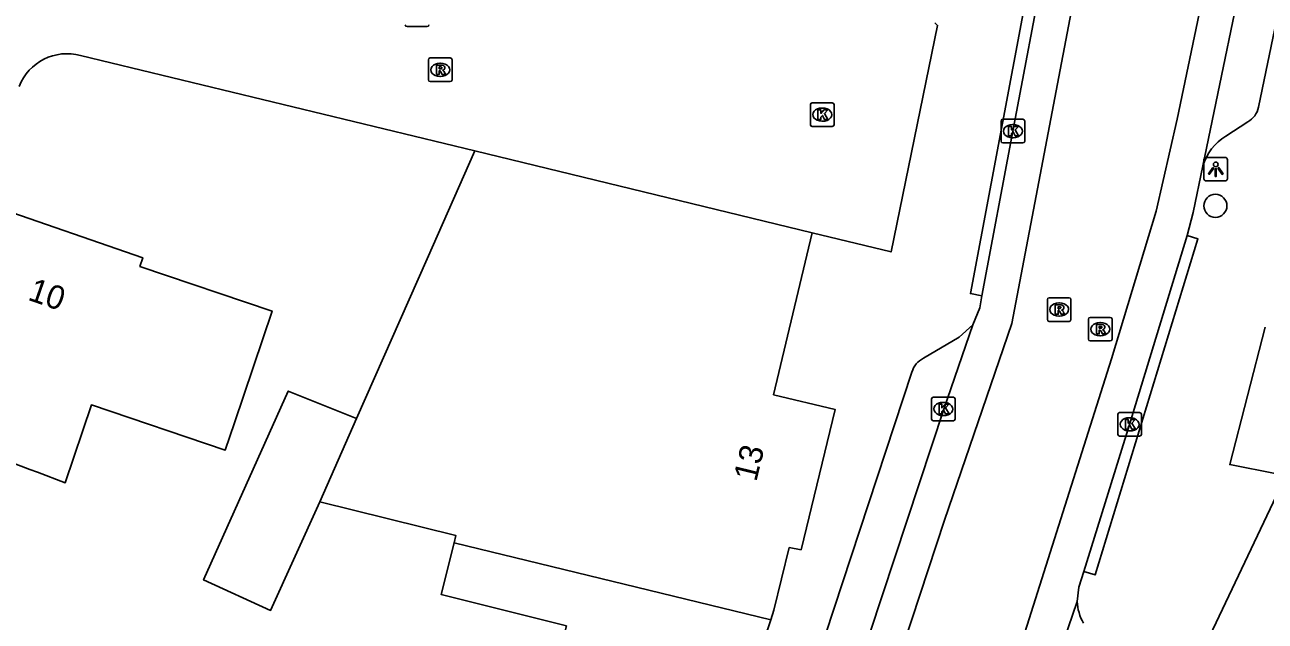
# Model space of a CAD drawing. Extents: x 160037 to 160839, y 385326 to 386441.
# Drawn here: x 160667.7 to 160720.3, y 385444.3 to 385469.6 of the extents above; entities that cross this region are included whole.
import ezdxf

# ---------------------------------------------------------------- set-up
doc = ezdxf.new("R2010")
doc.units = 0
for name, color, linetype in [('IMGEO_Boom', 7, 'Continuous'), ('IMGEO_Kolk', 7, 'Continuous'), ('IMGEO_Lichtpunt', 7, 'Continuous'), ('IMGEO_Pand', 7, 'Continuous'), ('IMGEO_Pand_nummerreeks', 7, 'Continuous'), ('IMGEO_Rijbaan_lokaal_gesloten', 7, 'Continuous'), ('IMGEO_Rijbaan_lokaal_open', 7, 'Continuous'), ('IMGEO_Rioolput', 7, 'Continuous'), ('IMGEO_Voetpad_open', 7, 'Continuous')]:
    doc.layers.add(name, color=color, linetype=linetype)

msp = doc.modelspace()

# ---------------------------------------------------------------- linework, layer by layer
at = {"layer": 'IMGEO_Boom'}
msp.add_circle((160718.188, 385461.911), 0.489, dxfattribs=at)
at = {"layer": 'IMGEO_Kolk'}
for p, q in [((160684.75, 385469.514), (160683.898, 385469.514)), ((160701.008, 385465.353), (160701.008, 385466.205)), ((160701.083, 385466.279), (160701.935, 385466.279)), ((160701.496, 385466.059), (160701.521, 385466.059)), ((160702.009, 385466.205), (160702.009, 385465.353)), ((160701.519, 385465.499), (160701.494, 385465.499)), ((160709.095, 385464.655), (160709.095, 385465.507)), ((160709.17, 385465.581), (160710.022, 385465.581)), ((160709.583, 385465.361), (160709.608, 385465.361)), ((160710.096, 385465.507), (160710.096, 385464.655)), ((160701.935, 385465.279), (160701.083, 385465.279)), ((160710.022, 385464.581), (160709.17, 385464.581)), ((160709.606, 385464.801), (160709.581, 385464.801)), ((160706.22, 385453.795), (160707.072, 385453.795)), ((160706.145, 385452.869), (160706.145, 385453.721)), ((160706.633, 385453.575), (160706.658, 385453.575)), ((160707.146, 385453.721), (160707.146, 385452.869)), ((160707.072, 385452.795), (160706.22, 385452.795)), ((160706.656, 385453.015), (160706.631, 385453.015)), ((160714.047, 385452.218), (160714.047, 385453.07)), ((160714.122, 385453.144), (160714.974, 385453.144)), ((160714.535, 385452.924), (160714.56, 385452.924)), ((160715.048, 385453.07), (160715.048, 385452.218)), ((160714.558, 385452.364), (160714.533, 385452.364)), ((160714.974, 385452.144), (160714.122, 385452.144))]:
    msp.add_line(p, q, dxfattribs=at)
for points in [[(160684.75, 385469.514), (160683.898, 385469.514)], [(160701.008, 385465.353), (160701.008, 385466.205)], [(160701.083, 385466.279), (160701.935, 385466.279)], [(160701.329, 385465.979), (160701.452, 385465.979), (160701.452, 385465.828), (160701.582, 385465.979), (160701.746, 385465.979), (160701.6, 385465.828), (160701.753, 385465.579), (160701.601, 385465.579), (160701.516, 385465.743), (160701.452, 385465.676), (160701.452, 385465.579), (160701.329, 385465.579), (160701.329, 385465.979)], [(160702.009, 385466.205), (160702.009, 385465.353)], [(160709.095, 385464.655), (160709.095, 385465.507)], [(160709.17, 385465.581), (160710.022, 385465.581)], [(160710.096, 385465.507), (160710.096, 385464.655)], [(160701.935, 385465.279), (160701.083, 385465.279)], [(160709.416, 385465.281), (160709.539, 385465.281), (160709.539, 385465.13), (160709.669, 385465.281), (160709.833, 385465.281), (160709.687, 385465.13), (160709.84, 385464.881), (160709.688, 385464.881), (160709.603, 385465.045), (160709.539, 385464.978), (160709.539, 385464.881), (160709.416, 385464.881), (160709.416, 385465.281)], [(160710.022, 385464.581), (160709.17, 385464.581)], [(160706.22, 385453.795), (160707.072, 385453.795)], [(160706.145, 385452.869), (160706.145, 385453.721)], [(160706.466, 385453.495), (160706.589, 385453.495), (160706.589, 385453.344), (160706.719, 385453.495), (160706.883, 385453.495), (160706.737, 385453.344), (160706.89, 385453.095), (160706.738, 385453.095), (160706.653, 385453.259), (160706.589, 385453.192), (160706.589, 385453.095), (160706.466, 385453.095), (160706.466, 385453.495)], [(160707.146, 385453.721), (160707.146, 385452.869)], [(160707.072, 385452.795), (160706.22, 385452.795)], [(160714.047, 385452.218), (160714.047, 385453.07)], [(160714.122, 385453.144), (160714.974, 385453.144)], [(160714.368, 385452.844), (160714.491, 385452.844), (160714.491, 385452.693), (160714.621, 385452.844), (160714.785, 385452.844), (160714.639, 385452.693), (160714.792, 385452.444), (160714.64, 385452.444), (160714.555, 385452.608), (160714.491, 385452.541), (160714.491, 385452.444), (160714.368, 385452.444), (160714.368, 385452.844)], [(160715.048, 385453.07), (160715.048, 385452.218)], [(160714.974, 385452.144), (160714.122, 385452.144)]]:
    msp.add_lwpolyline(points, dxfattribs=at)
for centre, start, end in [((160683.9, 385469.59), 181.552, 268.448), ((160683.9, 385469.59), 181.552, 268.448), ((160684.748, 385469.59), 271.552, 358.448), ((160684.748, 385469.59), 271.552, 358.448), ((160701.085, 385466.203), 91.552, 178.448), ((160701.085, 385466.203), 91.552, 178.448), ((160701.933, 385466.203), 1.552, 88.448), ((160701.933, 385466.203), 1.552, 88.448), ((160701.085, 385465.355), 181.552, 268.448), ((160701.085, 385465.355), 181.552, 268.448), ((160701.933, 385465.355), 271.552, 358.448), ((160701.933, 385465.355), 271.552, 358.448), ((160709.172, 385465.505), 91.552, 178.448), ((160709.172, 385465.505), 91.552, 178.448), ((160710.02, 385465.505), 1.552, 88.448), ((160710.02, 385465.505), 1.552, 88.448), ((160709.172, 385464.657), 181.552, 268.448), ((160709.172, 385464.657), 181.552, 268.448), ((160710.02, 385464.657), 271.552, 358.448), ((160710.02, 385464.657), 271.552, 358.448), ((160706.222, 385453.719), 91.552, 178.448), ((160706.222, 385453.719), 91.552, 178.448), ((160707.07, 385453.719), 1.552, 88.448), ((160707.07, 385453.719), 1.552, 88.448), ((160706.222, 385452.871), 181.552, 268.448), ((160706.222, 385452.871), 181.552, 268.448), ((160707.07, 385452.871), 271.552, 358.448), ((160707.07, 385452.871), 271.552, 358.448), ((160714.124, 385453.068), 91.552, 178.448), ((160714.124, 385453.068), 91.552, 178.448), ((160714.972, 385453.068), 1.552, 88.448), ((160714.972, 385453.068), 1.552, 88.448), ((160714.124, 385452.22), 181.552, 268.448), ((160714.124, 385452.22), 181.552, 268.448), ((160714.972, 385452.22), 271.552, 358.448), ((160714.972, 385452.22), 271.552, 358.448)]:
    msp.add_arc(centre, 0.0765, start, end, dxfattribs=at)
for centre, major_axis, ratio, start_param, end_param in [((160701.495, 385465.779), (-0.387, 0.002), 0.722429, 4.712389, 7.853982), ((160701.52, 385465.779), (-0.39, 0.002), 0.717154, 1.570796, 4.712389), ((160709.582, 385465.081), (-0.387, 0.002), 0.722429, 4.712389, 7.853982), ((160709.607, 385465.081), (-0.39, 0.002), 0.717154, 1.570796, 4.712389), ((160706.632, 385453.295), (-0.387, 0.002), 0.722429, 4.712389, 7.853982), ((160706.657, 385453.295), (-0.39, 0.002), 0.717154, 1.570796, 4.712389), ((160714.534, 385452.644), (-0.387, 0.002), 0.722429, 4.712389, 7.853982), ((160714.559, 385452.644), (-0.39, 0.002), 0.717154, 1.570796, 4.712389)]:
    msp.add_ellipse(centre, major_axis=major_axis, ratio=ratio, start_param=start_param, end_param=end_param, dxfattribs=at)
at = {"layer": 'IMGEO_Lichtpunt'}
for p, q in [((160717.702, 385463.868), (160717.702, 385463.061)), ((160717.702, 385463.868), (160717.702, 385463.061)), ((160718.604, 385463.963), (160717.796, 385463.963)), ((160718.604, 385463.963), (160717.796, 385463.963)), ((160718.698, 385463.061), (160718.698, 385463.868)), ((160718.698, 385463.061), (160718.698, 385463.868)), ((160717.796, 385462.967), (160718.604, 385462.967)), ((160717.796, 385462.967), (160718.604, 385462.967))]:
    msp.add_line(p, q, dxfattribs=at)
for points in [[(160718.076, 385463.532), (160718.115, 385463.504), (160717.927, 385463.242), (160717.889, 385463.269), (160718.076, 385463.532)], [(160718.178, 385463.484), (160718.225, 385463.484), (160718.225, 385463.162), (160718.178, 385463.162), (160718.178, 385463.484)], [(160718.288, 385463.504), (160718.326, 385463.531), (160718.513, 385463.269), (160718.474, 385463.241), (160718.288, 385463.504)]]:
    msp.add_lwpolyline(points, dxfattribs=at)
msp.add_circle((160718.201, 385463.666), 0.0994, dxfattribs=at)
for centre, start, end in [((160717.796, 385463.868), 90, 180), ((160717.796, 385463.868), 90, 180), ((160718.604, 385463.868), 0, 90), ((160718.604, 385463.868), 0, 90), ((160717.796, 385463.061), 180, 270), ((160717.796, 385463.061), 180, 270), ((160718.604, 385463.061), 270, 0), ((160718.604, 385463.061), 270, 360)]:
    msp.add_arc(centre, 0.0946, start, end, dxfattribs=at)
at = {"layer": 'IMGEO_Pand'}
for points in [[(160681.758, 385452.889), (160684.749, 385459.664), (160686.769, 385464.238)], [(160701.081, 385460.769), (160686.769, 385464.238)], [(160666.377, 385461.884), (160672.687, 385459.709), (160672.563, 385459.34), (160678.174, 385457.45), (160676.578, 385452.712), (160676.189, 385451.556), (160670.512, 385453.469), (160669.4, 385450.17), (160668.215, 385450.615), (160667.903, 385450.732), (160667.042, 385451.055), (160666.812, 385450.423), (160666.627, 385449.911), (160666.038, 385448.288), (160663.09, 385449.283), (160662.224, 385449.557), (160666.377, 385461.884)], [(160699.328, 385444.361), (160699.463, 385444.758), (160700.107, 385447.418), (160700.612, 385447.327), (160702.051, 385453.278), (160699.442, 385453.9), (160701.081, 385460.769)], [(160680.2, 385449.359), (160678.107, 385444.753), (160675.266, 385446.044), (160678.857, 385454.058), (160681.758, 385452.889)], [(160681.758, 385452.889), (160680.2, 385449.359)], [(160685.894, 385447.621), (160685.971, 385447.927), (160680.2, 385449.359)], [(160697.856, 385440.02), (160693.008, 385441.24), (160690.122, 385441.967), (160690.658, 385444.096), (160685.343, 385445.434), (160685.894, 385447.621)], [(160699.328, 385444.361), (160685.894, 385447.621)], [(160697.856, 385440.02), (160699.328, 385444.361)]]:
    msp.add_lwpolyline(points, dxfattribs=at)
at = {"layer": 'IMGEO_Rijbaan_lokaal_gesloten'}
for points in [[(160690.447, 385399.194), (160706.697, 385448.575), (160709.556, 385456.928), (160712.459, 385472.214), (160719.187, 385500), (160719.283, 385500.396)], [(160723.639, 385499.449), (160716.569, 385465.593), (160715.669, 385461.679), (160713.786, 385455.424), (160707.954, 385437.031), (160694.523, 385397.769)], [(160725.06, 385499.141), (160724.626, 385497.095), (160719.791, 385473.917), (160717.66, 385463.602)], [(160710.963, 385472.336), (160709.594, 385465.081), (160708.283, 385458.1)], [(160717.66, 385463.602), (160717.24, 385461.622), (160716.992, 385460.652)], [(160712.604, 385446.405), (160714.549, 385452.643), (160716.992, 385460.652)], [(160708.283, 385458.1), (160708.191, 385457.591), (160707.895, 385456.866)], [(160688.951, 385399.714), (160690.313, 385403.559), (160696.35, 385421.936), (160701.443, 385437.493), (160706.661, 385453.29), (160707.895, 385456.866)], [(160712.604, 385446.405), (160712.4, 385445.745), (160712.326, 385445.138)], [(160712.326, 385445.138), (160709.47, 385436.771), (160703.7, 385419.94), (160695.958, 385397.266)]]:
    msp.add_lwpolyline(points, dxfattribs=at)
at = {"layer": 'IMGEO_Rijbaan_lokaal_open'}
for points in [[(160701.081, 385460.769), (160704.431, 385459.957), (160706.404, 385469.564), (160706.283, 385469.675)], [(160686.769, 385464.238), (160670.05, 385468.291)], [(160720.793, 385450.546), (160718.792, 385450.935), (160720.304, 385456.764)]]:
    msp.add_lwpolyline(points, dxfattribs=at)
msp.add_arc((160669.485, 385466.163), 2.201, 75.1308, 158.28, dxfattribs=at)
at = {"layer": 'IMGEO_Rioolput'}
for p, q in [((160684.804, 385467.255), (160684.804, 385468.107)), ((160684.879, 385468.181), (160685.731, 385468.181)), ((160685.805, 385468.107), (160685.805, 385467.255)), ((160685.292, 385467.961), (160685.317, 385467.961)), ((160685.731, 385467.181), (160684.879, 385467.181)), ((160685.315, 385467.401), (160685.29, 385467.401)), ((160711.134, 385458.011), (160711.986, 385458.011)), ((160711.059, 385457.085), (160711.059, 385457.937)), ((160711.547, 385457.791), (160711.572, 385457.791)), ((160712.06, 385457.937), (160712.06, 385457.085)), ((160711.986, 385457.011), (160711.134, 385457.011)), ((160711.57, 385457.231), (160711.545, 385457.231)), ((160712.801, 385456.254), (160712.801, 385457.106)), ((160712.876, 385457.18), (160713.728, 385457.18)), ((160713.289, 385456.96), (160713.314, 385456.96)), ((160713.802, 385457.106), (160713.802, 385456.254)), ((160713.728, 385456.18), (160712.876, 385456.18)), ((160713.312, 385456.4), (160713.287, 385456.4))]:
    msp.add_line(p, q, dxfattribs=at)
for points in [[(160684.804, 385467.255), (160684.804, 385468.107)], [(160684.879, 385468.181), (160685.731, 385468.181)], [(160685.805, 385468.107), (160685.805, 385467.255)], [(160685.393, 385467.879), (160685.141, 385467.881), (160685.141, 385467.481)], [(160685.141, 385467.481), (160685.265, 385467.481), (160685.265, 385467.643), (160685.276, 385467.643)], [(160685.319, 385467.8), (160685.265, 385467.8), (160685.265, 385467.719)], [(160685.265, 385467.719), (160685.317, 385467.719)], [(160685.323, 385467.614), (160685.394, 385467.481), (160685.534, 385467.481), (160685.469, 385467.607)], [(160685.731, 385467.181), (160684.879, 385467.181)], [(160711.134, 385458.011), (160711.986, 385458.011)], [(160711.059, 385457.085), (160711.059, 385457.937)], [(160711.648, 385457.709), (160711.396, 385457.711), (160711.396, 385457.311)], [(160711.396, 385457.311), (160711.52, 385457.311), (160711.52, 385457.473), (160711.531, 385457.473)], [(160711.574, 385457.63), (160711.52, 385457.63), (160711.52, 385457.549)], [(160711.52, 385457.549), (160711.572, 385457.549)], [(160712.06, 385457.937), (160712.06, 385457.085)], [(160711.986, 385457.011), (160711.134, 385457.011)], [(160711.578, 385457.444), (160711.649, 385457.311), (160711.789, 385457.311), (160711.724, 385457.437)], [(160712.801, 385456.254), (160712.801, 385457.106)], [(160712.876, 385457.18), (160713.728, 385457.18)], [(160713.802, 385457.106), (160713.802, 385456.254)], [(160713.39, 385456.878), (160713.138, 385456.88), (160713.138, 385456.48)], [(160713.138, 385456.48), (160713.262, 385456.48), (160713.262, 385456.642), (160713.273, 385456.642)], [(160713.316, 385456.799), (160713.262, 385456.799), (160713.262, 385456.718)], [(160713.262, 385456.718), (160713.314, 385456.718)], [(160713.32, 385456.613), (160713.391, 385456.48), (160713.531, 385456.48), (160713.466, 385456.606)], [(160713.728, 385456.18), (160712.876, 385456.18)]]:
    msp.add_lwpolyline(points, dxfattribs=at)
for centre, radius, start, end in [((160684.881, 385468.105), 0.0765, 91.552, 178.448), ((160684.881, 385468.105), 0.0765, 91.552, 178.448), ((160685.729, 385468.105), 0.0765, 1.552, 88.448), ((160685.729, 385468.105), 0.0765, 1.552, 88.448), ((160685.275, 385467.59), 0.0533, 26.0293, 88.6989), ((160685.301, 385467.908), 0.19, 274.7715, 282.9687), ((160685.325, 385467.704), 0.0964, 77.0061, 93.1865), ((160685.339, 385467.761), 0.0378, 276.6634, 79.6772), ((160685.392, 385467.769), 0.109, 350.3612, 89.416), ((160685.39, 385467.769), 0.112, 277.5842, 350.9817), ((160685.374, 385467.554), 0.108, 29.5134, 73.7905), ((160684.881, 385467.257), 0.0765, 181.552, 268.448), ((160684.881, 385467.257), 0.0765, 181.552, 268.448), ((160685.729, 385467.257), 0.0765, 271.552, 358.448), ((160685.729, 385467.257), 0.0765, 271.552, 358.448), ((160711.136, 385457.935), 0.0765, 91.552, 178.448), ((160711.136, 385457.935), 0.0765, 91.552, 178.448), ((160711.984, 385457.935), 0.0765, 1.552, 88.448), ((160711.984, 385457.935), 0.0765, 1.552, 88.448), ((160711.53, 385457.42), 0.0533, 26.0293, 88.6989), ((160711.556, 385457.738), 0.19, 274.7715, 282.9687), ((160711.58, 385457.534), 0.0964, 77.0061, 93.1865), ((160711.594, 385457.591), 0.0378, 276.6634, 79.6772), ((160711.647, 385457.599), 0.109, 350.3612, 89.416), ((160711.645, 385457.599), 0.112, 277.5842, 350.9817), ((160711.629, 385457.384), 0.108, 29.5134, 73.7905), ((160711.136, 385457.087), 0.0765, 181.552, 268.448), ((160711.136, 385457.087), 0.0765, 181.552, 268.448), ((160711.984, 385457.087), 0.0765, 271.552, 358.448), ((160711.984, 385457.087), 0.0765, 271.552, 358.448), ((160712.878, 385457.104), 0.0765, 91.552, 178.448), ((160712.878, 385457.104), 0.0765, 91.552, 178.448), ((160713.726, 385457.104), 0.0765, 1.552, 88.448), ((160713.726, 385457.104), 0.0765, 1.552, 88.448), ((160713.272, 385456.589), 0.0533, 26.0293, 88.6989), ((160713.298, 385456.907), 0.19, 274.7715, 282.9687), ((160713.322, 385456.703), 0.0964, 77.0061, 93.1865), ((160713.336, 385456.76), 0.0378, 276.6634, 79.6772), ((160713.389, 385456.768), 0.109, 350.3612, 89.416), ((160713.387, 385456.768), 0.112, 277.5842, 350.9817), ((160713.371, 385456.553), 0.108, 29.5134, 73.7905), ((160712.878, 385456.256), 0.0765, 181.552, 268.448), ((160712.878, 385456.256), 0.0765, 181.552, 268.448), ((160713.726, 385456.256), 0.0765, 271.552, 358.448), ((160713.726, 385456.256), 0.0765, 271.552, 358.448)]:
    msp.add_arc(centre, radius, start, end, dxfattribs=at)
for centre, major_axis, ratio, start_param, end_param in [((160685.291, 385467.681), (-0.387, 0.002), 0.722429, 4.712389, 7.853982), ((160685.316, 385467.681), (-0.39, 0.002), 0.717154, 1.570796, 4.712389), ((160711.546, 385457.511), (-0.387, 0.002), 0.722429, 4.712389, 7.853982), ((160711.571, 385457.511), (-0.39, 0.002), 0.717154, 1.570796, 4.712389), ((160713.288, 385456.68), (-0.387, 0.002), 0.722429, 4.712389, 7.853982), ((160713.313, 385456.68), (-0.39, 0.002), 0.717154, 1.570796, 4.712389)]:
    msp.add_ellipse(centre, major_axis=major_axis, ratio=ratio, start_param=start_param, end_param=end_param, dxfattribs=at)
at = {"layer": 'IMGEO_Voetpad_open'}
for points in [[(160726.33, 385496.538), (160720.008, 385466.092)], [(160710.963, 385472.336), (160710.468, 385472.429), (160707.792, 385458.192), (160708.283, 385458.1)], [(160719.562, 385465.477), (160718.624, 385464.867)], [(160716.992, 385460.652), (160717.442, 385460.507), (160713.082, 385446.259), (160712.604, 385446.405)], [(160707.895, 385456.866), (160707.318, 385456.347), (160705.806, 385455.446)], [(160705.315, 385454.857), (160688.068, 385402.49)], [(160686.767, 385359.888), (160700.714, 385398.091), (160701.581, 385401.12), (160705.872, 385413.085), (160712.364, 385432.029), (160714.437, 385436.294), (160720.779, 385449.623)]]:
    msp.add_lwpolyline(points, dxfattribs=at)
for centre, radius, start, end in [((160719.155, 385466.242), 0.866, 298.0456, 350.0549), ((160719.825, 385462.952), 2.26, 122.0924, 163.2888), ((160706.19, 385454.626), 0.905, 115.1252, 165.2445), ((160714.283, 385445.203), 1.959, 181.9032, 210.3313)]:
    msp.add_arc(centre, radius, start, end, dxfattribs=at)

# ---------------------------------------------------------------- texts
at = {"layer": 'IMGEO_Pand_nummerreeks'}
for s, rotation, p in [('10', 340.9835, (160667.771, 385457.934)), ('13', 76.4064, (160698.71, 385450.18))]:
    msp.add_text(s, height=1, rotation=rotation, dxfattribs=at).set_placement(p)

doc.saveas('drawing.dxf')
